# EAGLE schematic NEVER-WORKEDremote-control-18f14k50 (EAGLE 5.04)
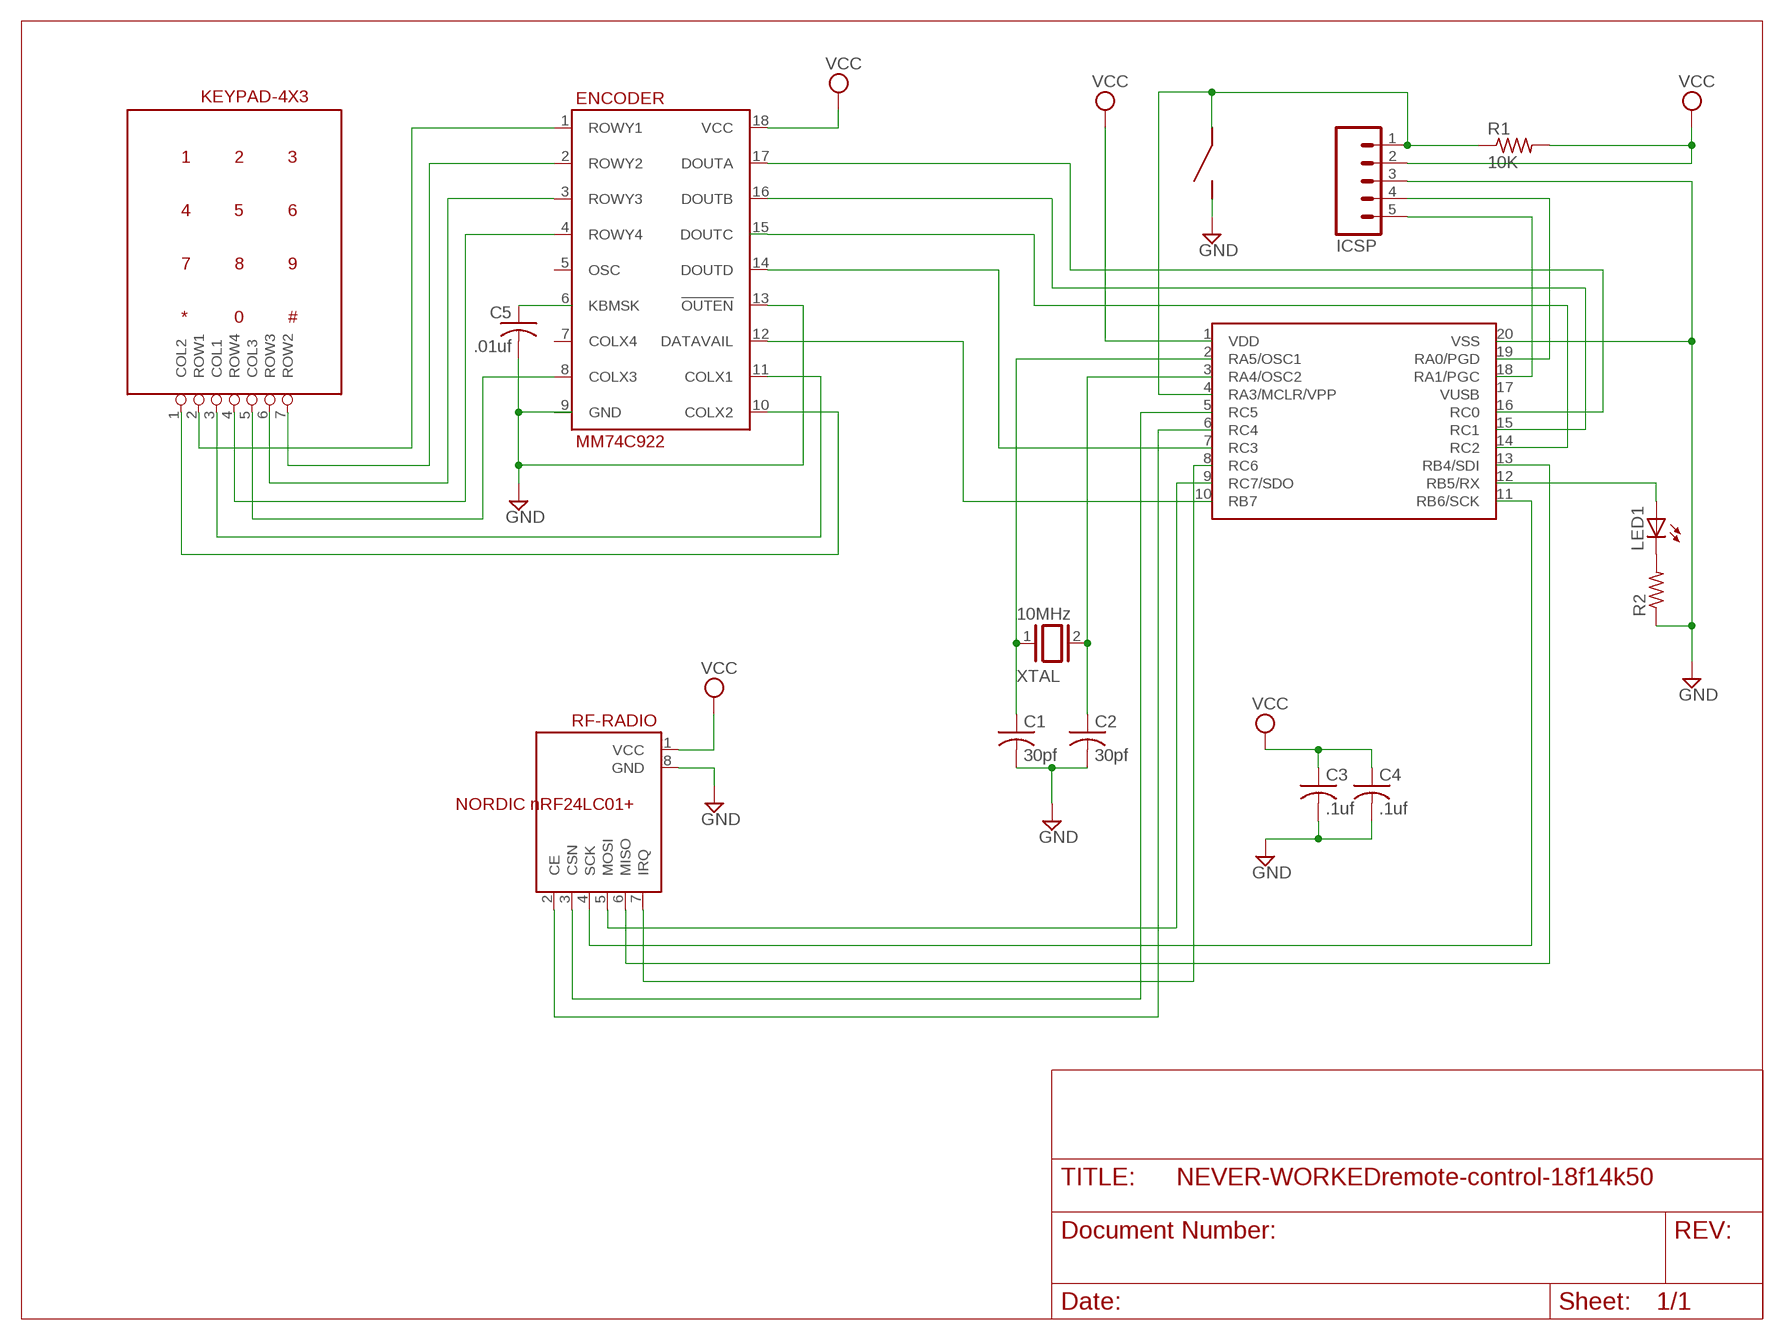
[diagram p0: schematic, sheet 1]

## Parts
C1  30pf  C-US102-043X133  [C102-043X133]
C2  30pf  C-US102-043X133  [C102-043X133]
C3  .1uf  C-US102-043X133  [C102-043X133]
C4  .1uf  C-US102-043X133  [C102-043X133]
C5  .01uf  C-US102-043X133  [C102-043X133]
ENCODER  MM74C922  [18DIL]
ICSP  M05  [05P]
KEYPAD-4X3  KEYPAD43  [4X3]
LED1  LED3MM  [LED3MM]
R1  10K  R-US_0617/22  [0617/22]
R2  R-US_0309/12  [0309/12]
RESET  PUSH-BUTTON-SWITCH  [2SIL]
RF-RADIO  NORDIC nRF24LC01+  NORDIC-BREAKOUT  [8SIL]
U$1  PIC18F14K50  [DIL20]
XTAL  10MHz  XTAL  [Q]

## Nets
GND: C1.2 C2.2 C3.2 C4.2 C5.2 ENCODER.9(GND) ENCODER.13(!OUTEN) ICSP.3 R2.1 RESET.NO RF-RADIO.8(GND) U$1.20(VSS)
N$1: ENCODER.10(COLX2) KEYPAD-4X3.1(COL2)
N$2: ENCODER.1(ROWY1) KEYPAD-4X3.2(ROW1)
N$3: ENCODER.11(COLX1) KEYPAD-4X3.3(COL1)
N$4: ENCODER.8(COLX3) KEYPAD-4X3.5(COL3)
N$5: ENCODER.4(ROWY4) KEYPAD-4X3.4(ROW4)
N$6: ENCODER.3(ROWY3) KEYPAD-4X3.6(ROW3)
N$7: ENCODER.2(ROWY2) KEYPAD-4X3.7(ROW2)
N$8: ENCODER.14(DOUTD) U$1.7(RC3)
N$9: C1.1 U$1.2(RA5/OSC1) XTAL.1
N$10: C2.1 U$1.3(RA4/OSC2) XTAL.2
N$11: ENCODER.12(DATAVAIL) U$1.10(RB7)
N$12: ENCODER.15(DOUTC) U$1.14(RC2)
N$13: ENCODER.16(DOUTB) U$1.15(RC1)
N$14: ENCODER.17(DOUTA) U$1.16(RC0)
N$15: ICSP.1 R1.1 RESET.COM U$1.4(RA3/MCLR/VPP)
N$16: ICSP.5 U$1.18(RA1/PGC)
N$17: U$1.19(RA0/PGD)
N$18: RF-RADIO.5(MOSI) U$1.9(RC7/SDO)
N$19: C5.1
N$20: RF-RADIO.7(IRQ) U$1.8(RC6)
N$21: LED1.K(C) R2.2
N$22: RF-RADIO.3(CSN) U$1.5(RC5)
N$23: RF-RADIO.6(MISO) U$1.13(RB4/SDI)
N$24: RF-RADIO.2(CE) U$1.6(RC4)
N$26: LED1.A U$1.12(RB5/RX)
N$28: RF-RADIO.4(SCK)
VCC: C3.1 C4.1 ENCODER.18(VCC) ICSP.2 R1.2 RF-RADIO.1(VCC) U$1.1(VDD)
Unconnected: ENCODER.5(OSC) ENCODER.6(KBMSK) ENCODER.7(COLX4) ICSP.4 U$1.11(RB6/SCK) U$1.17(VUSB)

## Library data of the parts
C1-C5 = rcl:C-US: CAPACITOR, American symbol
ENCODER = trl:MM74C922: 16-key encoder
ICSP = con-amp-quick:M05: AMP QUICK CONNECTOR
KEYPAD-4X3 = trl:KEYPAD43: 4x3 Keypad Input Device
LED1 = led:LED: LED
R1 R2 = resistor:R-US_: RESISTOR, American symbol
RESET = trl:PUSH-BUTTON-SWITCH
RF-RADIO = trl:NORDIC-BREAKOUT: Spark Fun Electronic's Nordic Semiconductor nRF24L01 with chip antenna
U$1 = trl:PIC18F14K50
XTAL = special:XTAL: CRYSTAL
